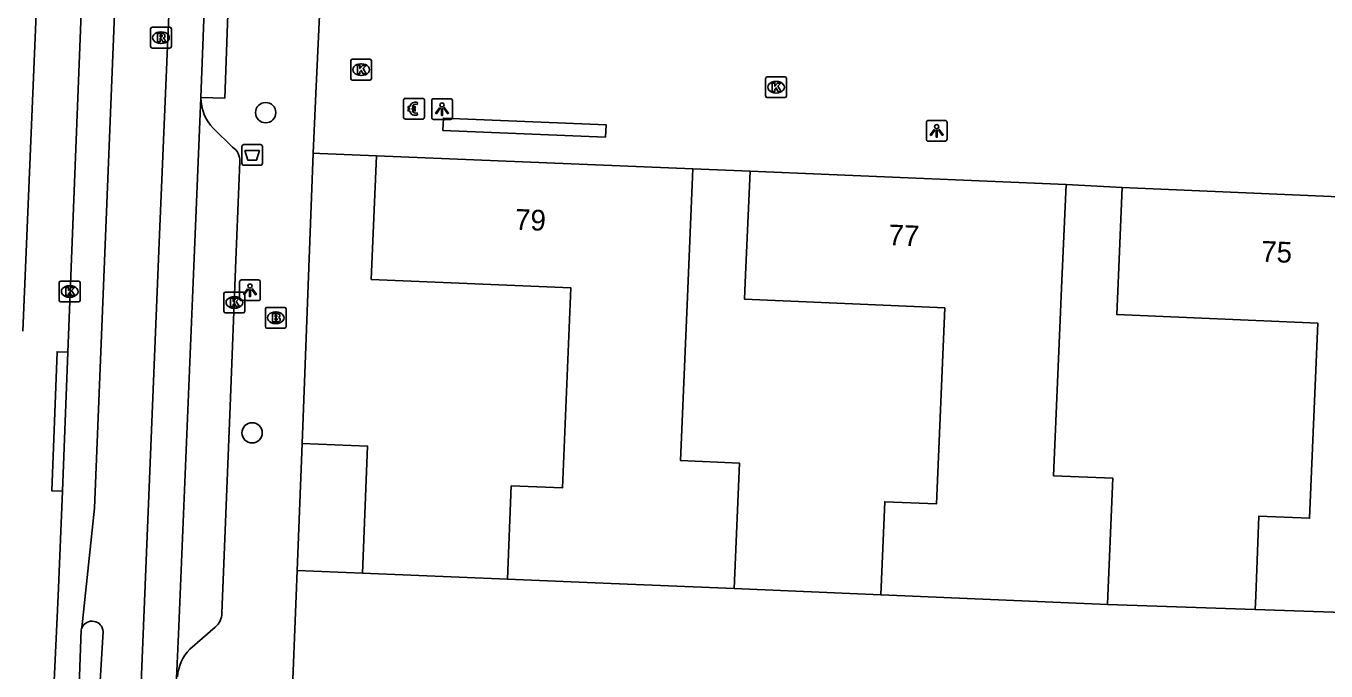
# Model space of a CAD drawing. Extents: x 160787 to 161428, y 386828 to 387483.
# Drawn here: x 161292.9 to 161355.6, y 386996.4 to 387027.5 of the extents above; entities that cross this region are included whole.
import ezdxf

# ---------------------------------------------------------------- set-up
doc = ezdxf.new("R2010")
doc.units = 0
for name, color, linetype in [('IMGEO_Afvalbak', 7, 'Continuous'), ('IMGEO_Betaalautomaat', 7, 'Continuous'), ('IMGEO_Boom', 7, 'Continuous'), ('IMGEO_Brandkraan', 7, 'Continuous'), ('IMGEO_Groenvoorziening', 7, 'Continuous'), ('IMGEO_Kolk', 7, 'Continuous'), ('IMGEO_Lichtpunt', 7, 'Continuous'), ('IMGEO_Muur', 7, 'Continuous'), ('IMGEO_Pand', 7, 'Continuous'), ('IMGEO_Pand_nummerreeks', 7, 'Continuous'), ('IMGEO_Rijbaan_lokaal_gesloten', 7, 'Continuous'), ('IMGEO_Rijbaan_lokaal_open', 7, 'Continuous'), ('IMGEO_Rioolput', 7, 'Continuous'), ('IMGEO_Voetpad_open', 7, 'Continuous')]:
    doc.layers.add(name, color=color, linetype=linetype)

msp = doc.modelspace()

# ---------------------------------------------------------------- linework, layer by layer
at = {"layer": 'IMGEO_Afvalbak'}
for p, q in [((161303.327, 387020.85), (161303.327, 387021.65)), ((161303.327, 387021.65), (161303.327, 387020.85)), ((161303.427, 387021.75), (161304.217, 387021.75)), ((161304.217, 387021.75), (161303.427, 387021.75)), ((161304.317, 387021.65), (161304.317, 387020.85)), ((161304.317, 387020.85), (161304.317, 387021.65)), ((161304.217, 387020.75), (161303.427, 387020.75)), ((161303.427, 387020.75), (161304.217, 387020.75))]:
    msp.add_line(p, q, dxfattribs=at)
msp.add_lwpolyline([(161303.47, 387021.464), (161304.174, 387021.464), (161304.025, 387020.994), (161303.619, 387020.994), (161303.47, 387021.464)], dxfattribs=at)
for centre, start, end in [((161303.427, 387021.65), 90, 180), ((161303.427, 387021.65), 90, 180), ((161304.217, 387021.65), 0, 90), ((161304.217, 387021.65), 360, 90), ((161303.427, 387020.85), 180, 270), ((161303.427, 387020.85), 180, 270), ((161304.217, 387020.85), 270, 0), ((161304.217, 387020.85), 270, 0)]:
    msp.add_arc(centre, 0.1, start, end, dxfattribs=at)
at = {"layer": 'IMGEO_Betaalautomaat'}
for p, q in [((161311.121, 387023.054), (161311.121, 387023.895)), ((161311.121, 387023.895), (161311.121, 387023.054)), ((161311.196, 387023.978), (161312.037, 387023.978)), ((161312.037, 387023.978), (161311.196, 387023.978)), ((161311.404, 387023.442), (161311.404, 387023.51)), ((161311.525, 387023.51), (161311.525, 387023.442)), ((161311.783, 387023.783), (161311.766, 387023.683)), ((161312.12, 387023.904), (161312.12, 387023.063)), ((161312.12, 387023.063), (161312.12, 387023.904)), ((161312.046, 387022.979), (161311.205, 387022.979)), ((161311.205, 387022.979), (161312.046, 387022.979)), ((161311.77, 387023.277), (161311.792, 387023.19))]:
    msp.add_line(p, q, dxfattribs=at)
for points in [[(161311.404, 387023.51), (161311.335, 387023.51), (161311.335, 387023.579), (161311.414, 387023.579)], [(161311.409, 387023.373), (161311.335, 387023.373), (161311.335, 387023.442), (161311.404, 387023.442)], [(161311.536, 387023.579), (161311.683, 387023.579), (161311.683, 387023.51), (161311.525, 387023.51)], [(161311.525, 387023.442), (161311.683, 387023.442), (161311.683, 387023.373), (161311.539, 387023.373)]]:
    msp.add_lwpolyline(points, dxfattribs=at)
for centre, radius, start, end in [((161311.199, 387023.901), 0.0779, 92.4484, 184.28452), ((161311.199, 387023.901), 0.0779, 92.4484, 184.28452), ((161311.67, 387023.428), 0.267, 191.80956, 297.03891), ((161311.697, 387023.503), 0.293, 73.01398, 165.01395), ((161311.703, 387023.516), 0.179, 69.32359, 159.56827), ((161311.703, 387023.443), 0.179, 202.76249, 291.86925), ((161312.043, 387023.901), 0.0779, 2.4484, 94.28452), ((161312.043, 387023.901), 0.0779, 2.4484, 94.28452), ((161311.199, 387023.057), 0.0779, 182.4484, 274.28452), ((161311.199, 387023.057), 0.0779, 182.4484, 274.28452), ((161312.043, 387023.057), 0.0779, 272.4484, 4.28452), ((161312.043, 387023.057), 0.0779, 272.4484, 4.28452)]:
    msp.add_arc(centre, radius, start, end, dxfattribs=at)
at = {"layer": 'IMGEO_Boom'}
for centre in [(161304.472, 387023.288), (161303.818, 387007.858)]:
    msp.add_circle(centre, 0.489, dxfattribs=at)
at = {"layer": 'IMGEO_Brandkraan'}
for p, q in [((161304.456, 387012.976), (161304.456, 387013.828)), ((161304.531, 387013.902), (161305.383, 387013.902)), ((161304.944, 387013.682), (161304.969, 387013.682)), ((161305.457, 387013.828), (161305.457, 387012.976)), ((161305.383, 387012.902), (161304.531, 387012.902)), ((161304.967, 387013.122), (161304.942, 387013.122))]:
    msp.add_line(p, q, dxfattribs=at)
for points in [[(161304.456, 387012.976), (161304.456, 387013.828)], [(161304.531, 387013.902), (161305.383, 387013.902)], [(161304.804, 387013.602), (161304.804, 387013.202), (161305.017, 387013.202)], [(161305.035, 387013.602), (161304.804, 387013.602)], [(161304.983, 387013.521), (161304.929, 387013.521), (161304.929, 387013.445)], [(161304.929, 387013.445), (161304.982, 387013.445)], [(161304.991, 387013.369), (161304.929, 387013.369), (161304.929, 387013.288)], [(161305.457, 387013.828), (161305.457, 387012.976)], [(161305.383, 387012.902), (161304.531, 387012.902)], [(161304.929, 387013.288), (161304.991, 387013.288)]]:
    msp.add_lwpolyline(points, dxfattribs=at)
for centre, radius, start, end in [((161304.533, 387013.826), 0.0765, 91.55205, 178.44795), ((161304.533, 387013.826), 0.0765, 91.55205, 178.44795), ((161304.984, 387013.483), 0.0379, 267.82845, 90.93552), ((161304.992, 387013.328), 0.0404, 269.87594, 90.50774), ((161305.039, 387013.457), 0.145, 59.4692, 91.53667), ((161305.064, 387013.504), 0.0922, 285.51372, 58.15012), ((161305.069, 387013.312), 0.105, 301.31148, 78.98903), ((161305.381, 387013.826), 0.0765, 1.55205, 88.44795), ((161305.381, 387013.826), 0.0765, 1.55205, 88.44795), ((161304.533, 387012.978), 0.0765, 181.55205, 268.44795), ((161304.533, 387012.978), 0.0765, 181.55205, 268.44795), ((161305.023, 387013.453), 0.251, 268.66757, 293.53466), ((161305.381, 387012.978), 0.0765, 271.55205, 358.44795), ((161305.381, 387012.978), 0.0765, 271.55205, 358.44795)]:
    msp.add_arc(centre, radius, start, end, dxfattribs=at)
for centre, major_axis, ratio, start_param, end_param in [((161304.943, 387013.402), (-0.387, 0.002), 0.722429, 4.712389, 7.853982), ((161304.968, 387013.402), (-0.39, 0.002), 0.717154, 1.570796, 4.712389)]:
    msp.add_ellipse(centre, major_axis=major_axis, ratio=ratio, start_param=start_param, end_param=end_param, dxfattribs=at)
at = {"layer": 'IMGEO_Groenvoorziening'}
for points in [[(161309.14, 387001.096), (161316.124, 387000.805)], [(161327.057, 387000.352), (161334.12, 387000.049)], [(161345.043, 386999.585), (161352.162, 386999.342)]]:
    msp.add_lwpolyline(points, dxfattribs=at)
at = {"layer": 'IMGEO_Kolk'}
for p, q in [((161308.572, 387024.935), (161308.572, 387025.787)), ((161308.647, 387025.861), (161309.499, 387025.861)), ((161309.06, 387025.641), (161309.085, 387025.641)), ((161309.573, 387025.787), (161309.573, 387024.935)), ((161309.499, 387024.861), (161308.647, 387024.861)), ((161309.083, 387025.081), (161309.058, 387025.081)), ((161328.569, 387024.088), (161328.569, 387024.94)), ((161328.644, 387025.014), (161329.496, 387025.014)), ((161329.057, 387024.794), (161329.082, 387024.794)), ((161329.57, 387024.94), (161329.57, 387024.088)), ((161329.496, 387024.014), (161328.644, 387024.014)), ((161329.08, 387024.234), (161329.055, 387024.234)), ((161294.526, 387014.243), (161294.526, 387015.095)), ((161294.601, 387015.169), (161295.453, 387015.169)), ((161295.014, 387014.949), (161295.039, 387014.949)), ((161295.527, 387015.095), (161295.527, 387014.243)), ((161302.537, 387014.64), (161303.389, 387014.64)), ((161295.453, 387014.169), (161294.601, 387014.169)), ((161295.037, 387014.389), (161295.012, 387014.389)), ((161302.462, 387013.714), (161302.462, 387014.566)), ((161302.95, 387014.42), (161302.975, 387014.42)), ((161303.463, 387014.566), (161303.463, 387013.714)), ((161303.389, 387013.64), (161302.537, 387013.64)), ((161302.973, 387013.86), (161302.948, 387013.86))]:
    msp.add_line(p, q, dxfattribs=at)
for points in [[(161308.572, 387024.935), (161308.572, 387025.787)], [(161308.647, 387025.861), (161309.499, 387025.861)], [(161308.893, 387025.561), (161309.016, 387025.561), (161309.016, 387025.41), (161309.146, 387025.561), (161309.31, 387025.561), (161309.164, 387025.41), (161309.317, 387025.161), (161309.165, 387025.161), (161309.08, 387025.325), (161309.016, 387025.258), (161309.016, 387025.161), (161308.893, 387025.161), (161308.893, 387025.561)], [(161309.573, 387025.787), (161309.573, 387024.935)], [(161309.499, 387024.861), (161308.647, 387024.861)], [(161328.569, 387024.088), (161328.569, 387024.94)], [(161328.644, 387025.014), (161329.496, 387025.014)], [(161328.89, 387024.714), (161329.013, 387024.714), (161329.013, 387024.563), (161329.143, 387024.714), (161329.307, 387024.714), (161329.161, 387024.563), (161329.314, 387024.314), (161329.162, 387024.314), (161329.077, 387024.478), (161329.013, 387024.411), (161329.013, 387024.314), (161328.89, 387024.314), (161328.89, 387024.714)], [(161329.57, 387024.94), (161329.57, 387024.088)], [(161329.496, 387024.014), (161328.644, 387024.014)], [(161294.526, 387014.243), (161294.526, 387015.095)], [(161294.601, 387015.169), (161295.453, 387015.169)], [(161294.847, 387014.869), (161294.97, 387014.869), (161294.97, 387014.718), (161295.1, 387014.869), (161295.264, 387014.869), (161295.118, 387014.718), (161295.271, 387014.469), (161295.119, 387014.469), (161295.034, 387014.633), (161294.97, 387014.566), (161294.97, 387014.469), (161294.847, 387014.469), (161294.847, 387014.869)], [(161295.527, 387015.095), (161295.527, 387014.243)], [(161302.537, 387014.64), (161303.389, 387014.64)], [(161295.453, 387014.169), (161294.601, 387014.169)], [(161302.462, 387013.714), (161302.462, 387014.566)], [(161302.783, 387014.34), (161302.906, 387014.34), (161302.906, 387014.189), (161303.036, 387014.34), (161303.2, 387014.34), (161303.054, 387014.189), (161303.207, 387013.94), (161303.055, 387013.94), (161302.97, 387014.104), (161302.906, 387014.037), (161302.906, 387013.94), (161302.783, 387013.94), (161302.783, 387014.34)], [(161303.463, 387014.566), (161303.463, 387013.714)], [(161303.389, 387013.64), (161302.537, 387013.64)]]:
    msp.add_lwpolyline(points, dxfattribs=at)
for centre, start, end in [((161308.649, 387025.785), 91.55205, 178.44795), ((161308.649, 387025.785), 91.55205, 178.44795), ((161309.497, 387025.785), 1.55205, 88.44795), ((161309.497, 387025.785), 1.55205, 88.44795), ((161308.649, 387024.937), 181.55205, 268.44795), ((161308.649, 387024.937), 181.55205, 268.44795), ((161309.497, 387024.937), 271.55205, 358.44795), ((161309.497, 387024.937), 271.55205, 358.44795), ((161328.646, 387024.938), 91.55205, 178.44795), ((161328.646, 387024.938), 91.55205, 178.44795), ((161329.494, 387024.938), 1.55205, 88.44795), ((161329.494, 387024.938), 1.55205, 88.44795), ((161328.646, 387024.09), 181.55205, 268.44795), ((161328.646, 387024.09), 181.55205, 268.44795), ((161329.494, 387024.09), 271.55205, 358.44795), ((161329.494, 387024.09), 271.55205, 358.44795), ((161294.603, 387015.093), 91.55205, 178.44795), ((161294.603, 387015.093), 91.55205, 178.44795), ((161295.451, 387015.093), 1.55205, 88.44795), ((161295.451, 387015.093), 1.55205, 88.44795), ((161302.539, 387014.564), 91.55205, 178.44795), ((161302.539, 387014.564), 91.55205, 178.44795), ((161303.387, 387014.564), 1.55205, 88.44795), ((161303.387, 387014.564), 1.55205, 88.44795), ((161294.603, 387014.245), 181.55205, 268.44795), ((161294.603, 387014.245), 181.55205, 268.44795), ((161295.451, 387014.245), 271.55205, 358.44795), ((161295.451, 387014.245), 271.55205, 358.44795), ((161302.539, 387013.716), 181.55205, 268.44795), ((161302.539, 387013.716), 181.55205, 268.44795), ((161303.387, 387013.716), 271.55205, 358.44795), ((161303.387, 387013.716), 271.55205, 358.44795)]:
    msp.add_arc(centre, 0.0765, start, end, dxfattribs=at)
for centre, major_axis, ratio, start_param, end_param in [((161309.059, 387025.361), (-0.387, 0.002), 0.722429, 4.712389, 7.853982), ((161309.084, 387025.361), (-0.39, 0.002), 0.717154, 1.570796, 4.712389), ((161329.056, 387024.514), (-0.387, 0.002), 0.722429, 4.712389, 7.853982), ((161329.081, 387024.514), (-0.39, 0.002), 0.717154, 1.570796, 4.712389), ((161295.013, 387014.669), (-0.387, 0.002), 0.722429, 4.712389, 7.853982), ((161295.038, 387014.669), (-0.39, 0.002), 0.717154, 1.570796, 4.712389), ((161302.949, 387014.14), (-0.387, 0.002), 0.722429, 4.712389, 7.853982), ((161302.974, 387014.14), (-0.39, 0.002), 0.717154, 1.570796, 4.712389)]:
    msp.add_ellipse(centre, major_axis=major_axis, ratio=ratio, start_param=start_param, end_param=end_param, dxfattribs=at)
at = {"layer": 'IMGEO_Lichtpunt'}
for p, q in [((161312.473, 387023.863), (161312.473, 387023.056)), ((161312.473, 387023.863), (161312.473, 387023.056)), ((161313.375, 387023.958), (161312.567, 387023.958)), ((161313.375, 387023.958), (161312.567, 387023.958)), ((161313.469, 387023.056), (161313.469, 387023.863)), ((161313.469, 387023.056), (161313.469, 387023.863)), ((161312.567, 387022.962), (161313.375, 387022.962)), ((161312.567, 387022.962), (161313.375, 387022.962)), ((161336.314, 387022.816), (161336.314, 387022.009)), ((161336.314, 387022.816), (161336.314, 387022.009)), ((161337.216, 387022.911), (161336.408, 387022.911)), ((161337.216, 387022.911), (161336.408, 387022.911)), ((161337.31, 387022.009), (161337.31, 387022.816)), ((161337.31, 387022.009), (161337.31, 387022.816)), ((161336.408, 387021.915), (161337.216, 387021.915)), ((161336.408, 387021.915), (161337.216, 387021.915)), ((161304.118, 387015.228), (161303.31, 387015.228)), ((161304.118, 387015.228), (161303.31, 387015.228)), ((161303.216, 387015.133), (161303.216, 387014.326)), ((161303.216, 387015.133), (161303.216, 387014.326)), ((161304.212, 387014.326), (161304.212, 387015.133)), ((161304.212, 387014.326), (161304.212, 387015.133)), ((161303.31, 387014.232), (161304.118, 387014.232)), ((161303.31, 387014.232), (161304.118, 387014.232))]:
    msp.add_line(p, q, dxfattribs=at)
for points in [[(161312.847, 387023.527), (161312.886, 387023.499), (161312.698, 387023.237), (161312.66, 387023.264), (161312.847, 387023.527)], [(161312.949, 387023.479), (161312.996, 387023.479), (161312.996, 387023.157), (161312.949, 387023.157), (161312.949, 387023.479)], [(161313.059, 387023.499), (161313.097, 387023.526), (161313.284, 387023.264), (161313.245, 387023.236), (161313.059, 387023.499)], [(161336.688, 387022.48), (161336.727, 387022.452), (161336.539, 387022.19), (161336.501, 387022.217), (161336.688, 387022.48)], [(161336.79, 387022.432), (161336.837, 387022.432), (161336.837, 387022.11), (161336.79, 387022.11), (161336.79, 387022.432)], [(161336.9, 387022.452), (161336.938, 387022.479), (161337.125, 387022.217), (161337.086, 387022.189), (161336.9, 387022.452)], [(161303.59, 387014.797), (161303.629, 387014.769), (161303.441, 387014.507), (161303.403, 387014.534), (161303.59, 387014.797)], [(161303.692, 387014.749), (161303.739, 387014.749), (161303.739, 387014.427), (161303.692, 387014.427), (161303.692, 387014.749)], [(161303.802, 387014.769), (161303.84, 387014.796), (161304.027, 387014.534), (161303.988, 387014.506), (161303.802, 387014.769)]]:
    msp.add_lwpolyline(points, dxfattribs=at)
for centre in [(161312.972, 387023.661), (161336.813, 387022.614), (161303.715, 387014.931)]:
    msp.add_circle(centre, 0.0994, dxfattribs=at)
for centre, start, end in [((161312.567, 387023.863), 90, 180), ((161312.567, 387023.863), 90, 180), ((161313.375, 387023.863), 0, 90), ((161313.375, 387023.863), 0, 90), ((161312.567, 387023.056), 180, 270), ((161312.567, 387023.056), 180, 270), ((161313.375, 387023.056), 270, 0), ((161313.375, 387023.056), 270, 360), ((161336.408, 387022.816), 90, 180), ((161336.408, 387022.816), 90, 180), ((161337.216, 387022.816), 0, 90), ((161337.216, 387022.816), 0, 90), ((161336.408, 387022.009), 180, 270), ((161336.408, 387022.009), 180, 270), ((161337.216, 387022.009), 270, 0), ((161337.216, 387022.009), 270, 360), ((161303.31, 387015.133), 90, 180), ((161303.31, 387015.133), 90, 180), ((161304.118, 387015.133), 0, 90), ((161304.118, 387015.133), 0, 90), ((161303.31, 387014.326), 180, 270), ((161303.31, 387014.326), 180, 270), ((161304.118, 387014.326), 270, 0), ((161304.118, 387014.326), 270, 360)]:
    msp.add_arc(centre, 0.0946, start, end, dxfattribs=at)
at = {"layer": 'IMGEO_Muur'}
msp.add_lwpolyline([(161306.763, 387021.339), (161306.231, 387007.346)], dxfattribs=at)
at = {"layer": 'IMGEO_Pand'}
for points in [[(161309.806, 387021.211), (161309.558, 387015.25), (161319.171, 387014.851), (161318.77, 387005.201), (161316.311, 387005.304), (161316.124, 387000.805)], [(161309.806, 387021.211), (161325.056, 387020.578)], [(161327.057, 387000.352), (161327.305, 387006.402), (161324.472, 387006.518), (161324.8, 387014.409), (161324.849, 387015.583), (161325.056, 387020.578)], [(161327.814, 387020.467), (161327.601, 387015.472), (161327.551, 387014.292), (161337.2, 387013.881), (161336.798, 387004.432), (161334.311, 387004.538), (161334.12, 387000.049)], [(161327.814, 387020.467), (161343.045, 387019.819)], [(161345.043, 386999.585), (161345.06, 387000), (161345.293, 387005.676), (161342.448, 387005.793), (161342.783, 387013.669), (161342.832, 387014.824), (161343.045, 387019.819)], [(161345.756, 387019.68), (161345.542, 387014.685), (161345.494, 387013.553), (161355.185, 387013.139), (161354.783, 387003.743), (161352.344, 387003.847), (161352.189, 387000), (161352.162, 386999.342)], [(161345.756, 387019.68), (161361.04, 387019.026)], [(161305.991, 387001.219), (161306.231, 387007.346)], [(161309.14, 387001.096), (161309.38, 387007.223), (161306.231, 387007.346)], [(161305.991, 387001.219), (161309.14, 387001.096)], [(161316.124, 387000.805), (161321.12, 387000.598), (161327.057, 387000.352)], [(161334.12, 387000.049), (161335.274, 387000), (161345.043, 386999.585)], [(161352.162, 386999.342), (161362.951, 386998.982)]]:
    msp.add_lwpolyline(points, dxfattribs=at)
at = {"layer": 'IMGEO_Rijbaan_lokaal_gesloten'}
for points in [[(161300.938, 387054.844), (161299.353, 387017.413), (161294.661, 386902.681)], [(161298.285, 387055.038), (161296.227, 387004.228), (161295.615, 386998.468)], [(161295.788, 387033.414), (161294.936, 387011.744)], [(161301.348, 387024.011), (161301.576, 387029.9)], [(161298.691, 386958.606), (161298.922, 386964.506), (161300.177, 386996.031), (161300.266, 386998.149), (161301.03, 387016.276), (161301.348, 387024.011)], [(161294.936, 387011.744), (161294.673, 387005.041)], [(161294.673, 387005.041), (161294.475, 387000), (161293.996, 386989.734)], [(161295.438, 386994.355), (161295.578, 386998.354)], [(161296.639, 386998.283), (161296.391, 386994.299)]]:
    msp.add_lwpolyline(points, dxfattribs=at)
for centre, radius, start, end in [((161296.064, 386998.259), 0.495, 155.071, 168.96614), ((161296.103, 386998.245), 0.537, 4.02293, 155.49542)]:
    msp.add_arc(centre, radius, start, end, dxfattribs=at)
at = {"layer": 'IMGEO_Rijbaan_lokaal_open'}
for points in [[(161306.763, 387021.339), (161306.892, 387024.216), (161307.145, 387029.702)], [(161320.853, 387022.104), (161313.01, 387022.43), (161313.035, 387023.03), (161320.878, 387022.704), (161320.853, 387022.104)], [(161306.763, 387021.339), (161307.084, 387021.324), (161309.806, 387021.211)], [(161325.056, 387020.578), (161327.814, 387020.467)], [(161343.045, 387019.819), (161345.756, 387019.68)]]:
    msp.add_lwpolyline(points, dxfattribs=at)
at = {"layer": 'IMGEO_Rioolput'}
for p, q in [((161298.924, 387026.476), (161298.924, 387027.328)), ((161298.999, 387027.402), (161299.851, 387027.402)), ((161299.412, 387027.182), (161299.437, 387027.182)), ((161299.925, 387027.328), (161299.925, 387026.476)), ((161299.435, 387026.622), (161299.41, 387026.622)), ((161299.851, 387026.402), (161298.999, 387026.402))]:
    msp.add_line(p, q, dxfattribs=at)
for points in [[(161298.924, 387026.476), (161298.924, 387027.328)], [(161298.999, 387027.402), (161299.851, 387027.402)], [(161299.925, 387027.328), (161299.925, 387026.476)], [(161299.513, 387027.1), (161299.261, 387027.102), (161299.261, 387026.702)], [(161299.261, 387026.702), (161299.385, 387026.702), (161299.385, 387026.864), (161299.396, 387026.864)], [(161299.439, 387027.021), (161299.385, 387027.021), (161299.385, 387026.94)], [(161299.385, 387026.94), (161299.437, 387026.94)], [(161299.443, 387026.835), (161299.514, 387026.702), (161299.654, 387026.702), (161299.589, 387026.828)], [(161299.851, 387026.402), (161298.999, 387026.402)]]:
    msp.add_lwpolyline(points, dxfattribs=at)
for centre, radius, start, end in [((161299.001, 387027.326), 0.0765, 91.55205, 178.44795), ((161299.001, 387027.326), 0.0765, 91.55205, 178.44795), ((161299.849, 387027.326), 0.0765, 1.55205, 88.44795), ((161299.849, 387027.326), 0.0765, 1.55205, 88.44795), ((161299.395, 387026.811), 0.0533, 26.02933, 88.69889), ((161299.421, 387027.129), 0.19, 274.7715, 282.96867), ((161299.445, 387026.925), 0.0964, 77.00612, 93.18647), ((161299.459, 387026.982), 0.0378, 276.66336, 79.67722), ((161299.512, 387026.99), 0.109, 350.36119, 89.41601), ((161299.51, 387026.99), 0.112, 277.58423, 350.98172), ((161299.494, 387026.775), 0.108, 29.51342, 73.79051), ((161299.001, 387026.478), 0.0765, 181.55205, 268.44795), ((161299.001, 387026.478), 0.0765, 181.55205, 268.44795), ((161299.849, 387026.478), 0.0765, 271.55205, 358.44795), ((161299.849, 387026.478), 0.0765, 271.55205, 358.44795)]:
    msp.add_arc(centre, radius, start, end, dxfattribs=at)
for centre, major_axis, ratio, start_param, end_param in [((161299.411, 387026.902), (-0.387, 0.002), 0.722429, 4.712389, 7.853982), ((161299.436, 387026.902), (-0.39, 0.002), 0.717154, 1.570796, 4.712389)]:
    msp.add_ellipse(centre, major_axis=major_axis, ratio=ratio, start_param=start_param, end_param=end_param, dxfattribs=at)
at = {"layer": 'IMGEO_Voetpad_open'}
for points in [[(161292.771, 387012.758), (161293.577, 387031.886)], [(161301.576, 387029.9), (161302.708, 387029.836), (161302.503, 387023.985), (161301.348, 387024.011)], [(161301.956, 387022.522), (161302.88, 387021.628)], [(161303.227, 387020.931), (161303.04, 387016.186), (161302.763, 387009.137), (161302.366, 386999.17)], [(161306.231, 387007.346), (161306.763, 387021.339)], [(161294.673, 387005.041), (161294.166, 387005.058), (161294.419, 387011.762), (161294.936, 387011.744)], [(161305.522, 386989.524), (161305.942, 387000), (161305.991, 387001.219)], [(161302.043, 386998.5), (161300.823, 386997.435)]]:
    msp.add_lwpolyline(points, dxfattribs=at)
for centre, radius, start, end in [((161303.478, 387024.012), 2.13, 180.02721, 224.3959), ((161302.403, 387020.956), 0.824, 358.28543, 54.64722), ((161301.467, 386999.191), 0.899, 309.83255, 358.69099), ((161302.27, 386995.985), 2.049, 134.95894, 176.87792)]:
    msp.add_arc(centre, radius, start, end, dxfattribs=at)

# ---------------------------------------------------------------- texts
at = {"layer": 'IMGEO_Pand_nummerreeks'}
for s, rotation, p in [('79', 357.62312, (161316.47, 387017.652)), ('77', 357.56383, (161334.464, 387016.901)), ('75', 357.54982, (161352.432, 387016.111))]:
    msp.add_text(s, height=1, rotation=rotation, dxfattribs=at).set_placement(p)

doc.saveas('drawing.dxf')
